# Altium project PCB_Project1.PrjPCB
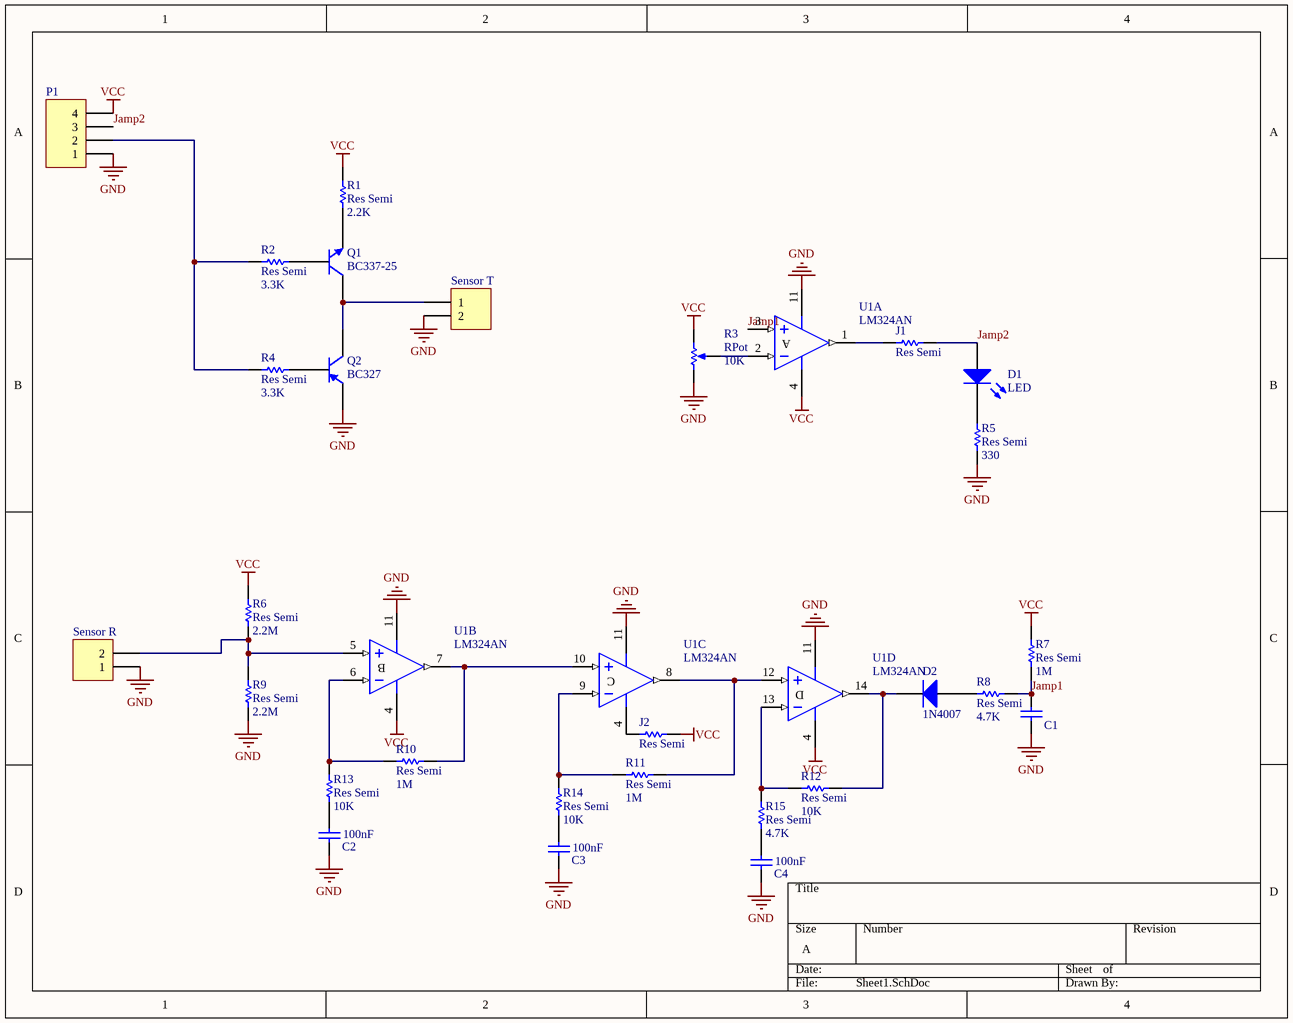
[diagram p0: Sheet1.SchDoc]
1 sheet, 29 parts. Net scope: global (net labels, ports and power ports of the same name join across sheets).
Board file: PCB1.PcbDoc

## Sheet Sheet1.SchDoc
size A; PageSetup: Record=PageOptions|CenterHorizontal=True|CenterVertical=True|PrintScale=1.09|XCorrection=1.00|YCorrection=1.00|PrintKind=0|BorderSize=5000000|LeftOffset=0|BottomOffset=0|Orientation=2|PaperLength=1000|PaperWidth=1000|Scale=100|PaperSource=7|PrintQuality=300|MediaType=1|DitherType=10|PaperKind=A4|PrintScaleMode=1

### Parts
C1  Cap  [My_cap100n]  (value not drawn)
C2  value 100nF  [My_cap100n]  (hidden comment: Cap)
C3  value 100nF  [My_cap100n]  (hidden comment: Cap)
C4  value 100nF  [My_cap100n]  (hidden comment: Cap)
D1  LED  [LED 5mm]
D2  1N4007  [My_DO-41]
J1  Res Semi  [Res 0.4]
J2  Res Semi  [Res 0.4]
P1  Header 4  [My_1X04]  (value not drawn)
Q1  BC337-25  [SOT54]
Q2  BC327  [29-04]
R1  Res Semi  value 2.2K  [Res 0.4]
R2  Res Semi  value 3.3K  [Res 0.4]
R3  RPot  value 10K  [multitran]
R4  Res Semi  value 3.3K  [Res 0.4]
R5  Res Semi  value 330  [Res 0.4]
R6  Res Semi  value 2.2M  [Res 0.4]
R7  Res Semi  value 1M  [Res 0.4]
R8  Res Semi  value 4.7K  [Res 0.4]
R9  Res Semi  value 2.2M  [Res 0.4]
R10  Res Semi  value 1M  [Res 0.4]
R11  Res Semi  value 1M  [Res 0.4]
R12  Res Semi  value 10K  [Res 0.4]
R13  Res Semi  value 10K  [Res 0.4]
R14  Res Semi  value 10K  [Res 0.4]
R15  Res Semi  value 4.7K  [Res 0.4]
Sensor_R  R  [My_1X02]  (value not drawn)
Sensor_T  T  [My_1X02]  (value not drawn)
U1  LM324AN  [DIP14]  (parts A,B,C,D of 4)

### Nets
GND: C1.1 C2.1 C3.1 C4.1 P1.1 Q2.3(E) R3.1(TOP) R5.1 R9.2 Sensor_R.1 Sensor_T.2 U1.11(V-)
VCC: J2.1 P1.4 R1.1 R3.3(TAP) R6.1 R7.2 U1.4(V+)
Jamp1: C1.2 R7.1 R8.2 U1.3(IN+)
Jamp2: D1.A J1.1 P1.3
NetC2_2: C2.2 R13.1
NetC3_2: C3.2 R14.1
NetC4_2: C4.2 R15.1
NetD1_K: D1.K R5.2
NetD2_A: D2.A R8.1
NetD2_K: D2.K R12.1 U1.14(OUT)
NetJ1_2: J1.2 U1.1(OUT)
NetJ2_2: J2.2 U1.4(V+)
NetP1_2: P1.2 R2.2 R4.2
NetQ1_1: Q1.1(E) R1.2
NetQ1_2: Q1.2(B) R2.1
NetQ1_3: Q1.3(C) Q2.1(C) Sensor_T.1
NetQ2_2: Q2.2(B) R4.1
NetR3_2: R3.2(BOT) U1.2(IN-)
NetR6_2: R6.2 R9.1 Sensor_R.2 U1.5(IN+)
NetR10_1: R10.1 U1.7(OUT) U1.10(IN+)
NetR10_2: R10.2 R13.2 U1.6(IN-)
NetR11_1: R11.1 U1.8(OUT) U1.12(IN+)
NetR11_2: R11.2 R14.2 U1.9(IN-)
NetR12_2: R12.2 R15.2 U1.13(IN-)

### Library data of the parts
C1 = Cap ceramic: CAP-100Nf; Value: 100nF
C2-C4 = Cap ceramic: CAP-100Nf
D1 = LED: Typical INFRARED GaAs LED
D2 = 1N4007: 1 Amp Diode
J1 J2 = Res Semi: Semiconductor Resistor; Value: 1K
P1 = Header 4: Header, 4-Pin
Q1 = BC337-25: NPN General-purpose Transistor
Q2 = BC327: Amplifier Transistor PNP Silicon
R1 R2 R4-R15 = Res Semi: Semiconductor Resistor
R3 = RPot: Potentiometer; Sim Note: Enter the Resistance value and the set point into parameter fields.; Set Position: 0.5
Sensor_R Sensor_T = Header 2: Header, 2-Pin
U1 = LM324AN: Low-Power Quad Operational Amplifier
